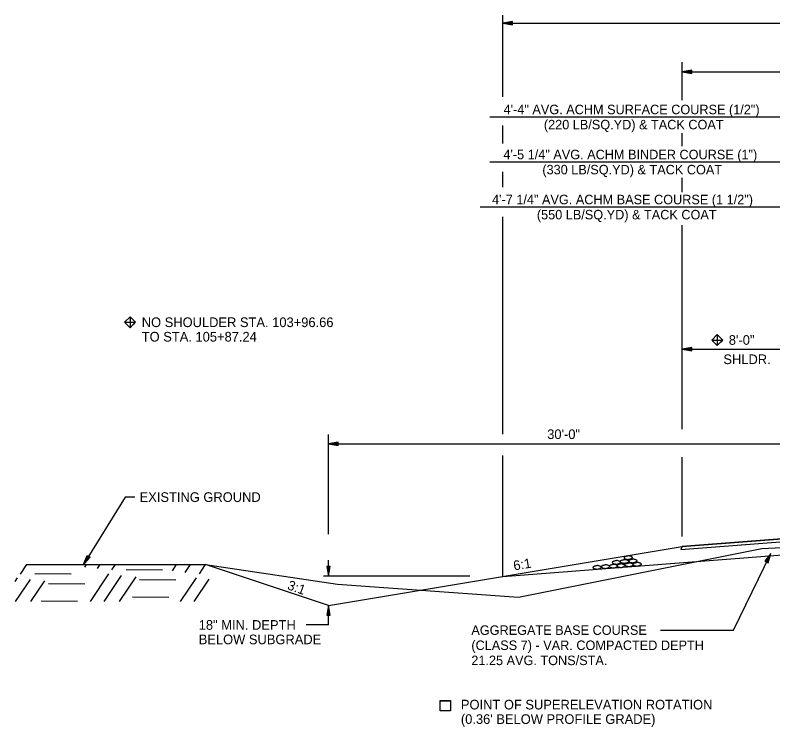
# Model space of a CAD drawing. Extents: x 1001270 to 1003428, y 1840152 to 1842912.
# Drawn here: x 1001282.03 to 1001329.17, y 1842384.9 to 1842429.16 of the extents above; entities that cross this region are included whole.
import ezdxf

# ---------------------------------------------------------------- set-up
doc = ezdxf.new("R2010")
doc.units = 0
for name, color, linetype in [('1', 7, 'Continuous'), ('10', 7, 'Continuous'), ('19', 7, 'Continuous')]:
    doc.layers.add(name, color=color, linetype=linetype)

# ---------------------------------------------------------------- blocks, each defined once
blk = doc.blocks.new('ROCKS')
at = {"layer": '1'}
blk.add_spline([(0.013, 0.06), (0.053, 0.053), (0.107, 0.033), (0.133, 0.013), (0.133, -0.007), (0.12, -0.033), (0.107, -0.04), (0.073, -0.053), (0.033, -0.067), (0.013, -0.067), (-0.02, -0.06), (-0.06, -0.053), (-0.087, -0.047), (-0.113, -0.02), (-0.113, -0.007), (-0.107, 0.02), (-0.087, 0.033), (-0.067, 0.047), (-0.033, 0.053), (-0.02, 0.06), (0.013, 0.06)], degree=3, dxfattribs=at)
blk = doc.blocks.new('4TO1 ABC')
at = {"layer": '1', "xscale": 0.1312491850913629, "yscale": 0.1312491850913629, "rotation": 180}
for p in [(0.00175, -0.00875), (-0.03325, -0.0385), (-0.016625, -0.023625), (0, -0.0385), (0.018375, -0.023625), (0.034125, -0.04025), (0.051625, -0.025375), (0.06475, -0.04025), (0.098, -0.04025), (0.133, -0.041125)]:
    blk.add_blockref('ROCKS', p, dxfattribs=at)

msp = doc.modelspace()

# ---------------------------------------------------------------- linework, layer by layer
at = {"layer": '10'}
for p, q in [((1001289.179, 1842410.399), (1001289.179, 1842409.719)), ((1001288.839, 1842410.059), (1001289.519, 1842410.059)), ((1001289.381, 1842409.921), (1001289.387, 1842409.927)), ((1001325.709, 1842409.294), (1001325.709, 1842408.614)), ((1001325.369, 1842408.954), (1001326.049, 1842408.954)), ((1001325.911, 1842408.816), (1001325.917, 1842408.822))]:
    msp.add_line(p, q, dxfattribs=at)
for points in [[(1001289.387, 1842409.927), (1001289.519, 1842410.059), (1001289.179, 1842410.399), (1001288.839, 1842410.059), (1001289.179, 1842409.719), (1001289.381, 1842409.921)], [(1001325.917, 1842408.822), (1001326.049, 1842408.954), (1001325.709, 1842409.294), (1001325.369, 1842408.954), (1001325.709, 1842408.614), (1001325.911, 1842408.816)]]:
    msp.add_lwpolyline(points, dxfattribs=at)
at = {"layer": '19'}
for p, q in [((1001312.371, 1842424.083), (1001312.371, 1842429.157)), ((1001312.971, 1842428.759), (1001312.371, 1842428.654)), ((1001312.371, 1842428.654), (1001368.525, 1842428.654)), ((1001312.371, 1842428.654), (1001312.971, 1842428.549)), ((1001312.971, 1842428.704), (1001312.531, 1842428.669)), ((1001312.531, 1842428.639), (1001312.971, 1842428.599)), ((1001312.971, 1842428.549), (1001312.971, 1842428.759)), ((1001323.525, 1842423.863), (1001323.525, 1842426.227)), ((1001324.125, 1842425.732), (1001323.525, 1842425.627)), ((1001323.525, 1842425.627), (1001324.125, 1842425.522)), ((1001323.525, 1842425.627), (1001367.525, 1842425.627)), ((1001324.125, 1842425.677), (1001323.685, 1842425.642)), ((1001323.685, 1842425.612), (1001324.125, 1842425.572)), ((1001324.125, 1842425.522), (1001324.125, 1842425.732)), ((1001331.395, 1842422.82), (1001311.553, 1842422.82)), ((1001312.371, 1842421.171), (1001312.371, 1842422.3)), ((1001323.525, 1842421.012), (1001323.525, 1842421.824)), ((1001331.286, 1842420.02), (1001311.553, 1842420.02)), ((1001312.371, 1842418.459), (1001312.371, 1842419.42)), ((1001323.525, 1842418.144), (1001323.525, 1842419.046)), ((1001331.113, 1842417.22), (1001310.964, 1842417.22)), ((1001312.371, 1842403.092), (1001312.371, 1842416.616)), ((1001323.525, 1842403.41), (1001323.525, 1842416.105)), ((1001324.125, 1842408.483), (1001323.525, 1842408.378)), ((1001323.525, 1842408.378), (1001331.525, 1842408.378)), ((1001323.525, 1842408.378), (1001324.125, 1842408.273)), ((1001324.125, 1842408.428), (1001323.685, 1842408.393)), ((1001323.685, 1842408.363), (1001324.125, 1842408.323)), ((1001324.125, 1842408.273), (1001324.125, 1842408.483)), ((1001301.519, 1842396.888), (1001301.519, 1842403.081)), ((1001302.119, 1842402.601), (1001301.519, 1842402.496)), ((1001301.519, 1842402.496), (1001331.519, 1842402.496)), ((1001301.519, 1842402.496), (1001302.119, 1842402.391)), ((1001302.119, 1842402.546), (1001301.679, 1842402.511)), ((1001301.679, 1842402.481), (1001302.119, 1842402.441)), ((1001302.119, 1842402.391), (1001302.119, 1842402.601)), ((1001312.371, 1842394.251), (1001312.371, 1842401.767)), ((1001323.525, 1842396.741), (1001323.525, 1842401.663)), ((1001301.519, 1842392.442), (1001323.525, 1842396.11)), ((1001323.525, 1842396.11), (1001323.438, 1842395.936)), ((1001326.721, 1842390.916), (1001329.041, 1842395.682)), ((1001329.041, 1842395.682), (1001328.677, 1842395.193)), ((1001328.864, 1842395.1), (1001329.041, 1842395.682)), ((1001286.292, 1842394.988), (1001286.516, 1842395.555)), ((1001286.693, 1842395.445), (1001286.292, 1842394.988)), ((1001286.366, 1842395.129), (1001286.559, 1842395.523)), ((1001286.652, 1842395.467), (1001286.389, 1842395.118)), ((1001286.516, 1842395.555), (1001286.693, 1842395.445)), ((1001301.519, 1842394.276), (1001301.519, 1842395.262)), ((1001328.677, 1842395.193), (1001328.864, 1842395.1)), ((1001328.959, 1842395.545), (1001328.726, 1842395.172)), ((1001328.82, 1842395.123), (1001328.984, 1842395.532)), ((1001282.373, 1842394.403), (1001282.764, 1842394.986)), ((1001286.358, 1842394.837), (1001286.464, 1842394.987)), ((1001287.153, 1842394.745), (1001287.319, 1842394.99)), ((1001288.048, 1842394.653), (1001288.274, 1842394.992)), ((1001288.936, 1842394.683), (1001291.196, 1842394.671)), ((1001291.812, 1842394.598), (1001292.074, 1842394.993)), ((1001292.607, 1842394.506), (1001292.939, 1842394.994)), ((1001293.502, 1842394.414), (1001293.883, 1842394.988)), ((1001301.519, 1842392.442), (1001293.883, 1842394.988)), ((1001301.624, 1842394.876), (1001301.414, 1842394.876)), ((1001301.414, 1842394.876), (1001301.519, 1842394.276)), ((1001301.464, 1842394.876), (1001301.504, 1842394.436)), ((1001301.519, 1842394.276), (1001301.624, 1842394.876)), ((1001301.534, 1842394.436), (1001301.569, 1842394.876)), ((1001283.261, 1842394.442), (1001285.521, 1842394.421)), ((1001286.71, 1842392.69), (1001287.862, 1842394.411)), ((1001287.565, 1842392.692), (1001288.657, 1842394.319)), ((1001288.52, 1842392.695), (1001289.552, 1842394.227)), ((1001310.315, 1842394.276), (1001301.204, 1842394.276)), ((1001282.033, 1842393.935), (1001282.187, 1842394.161)), ((1001282.055, 1842392.686), (1001282.982, 1842394.069)), ((1001283.01, 1842392.689), (1001283.877, 1842393.977)), ((1001284.101, 1842393.813), (1001286.361, 1842393.791)), ((1001289.766, 1842394.054), (1001292.036, 1842394.042)), ((1001292.32, 1842392.696), (1001293.316, 1842394.171)), ((1001293.175, 1842392.698), (1001294.111, 1842394.08)), ((1001289.324, 1842392.984), (1001291.584, 1842392.962)), ((1001283.648, 1842392.734), (1001285.919, 1842392.721)), ((1001301.519, 1842392.442), (1001301.414, 1842391.842)), ((1001301.624, 1842391.842), (1001301.519, 1842392.442)), ((1001301.519, 1842391.236), (1001301.519, 1842392.442)), ((1001301.504, 1842392.282), (1001301.469, 1842391.842)), ((1001301.574, 1842391.842), (1001301.534, 1842392.282)), ((1001301.414, 1842391.842), (1001301.624, 1842391.842)), ((1001301.519, 1842391.236), (1001300.136, 1842391.236)), ((1001322.186, 1842390.916), (1001326.721, 1842390.916))]:
    msp.add_line(p, q, dxfattribs=at)
for points in [[(1001282.728, 1842394.989), (1001293.883, 1842394.988), (1001302.082, 1842393.777), (1001313.349, 1842392.957), (1001328.479, 1842395.985), (1001332.634, 1842396.196), (1001337.518, 1842396.687), (1001349.673, 1842397.765), (1001361.518, 1842398.535), (1001365.857, 1842398.933), (1001373.504, 1842399.059), (1001376.059, 1842399.691), (1001380.152, 1842402.606), (1001384.463, 1842404.255), (1001389.111, 1842404.941), (1001392.065, 1842405.156)], [(1001323.525, 1842396.11), (1001349.525, 1842398.112), (1001367.525, 1842399.498)], [(1001289.475, 1842399.187), (1001288.875, 1842399.187), (1001286.292, 1842394.988)], [(1001323.438, 1842395.936), (1001349.525, 1842397.945), (1001367.525, 1842399.331)], [(1001312.371, 1842394.251), (1001337.518, 1842396.187)], [(1001309.108, 1842385.886), (1001308.467, 1842385.886), (1001308.467, 1842386.527), (1001309.108, 1842386.527), (1001309.108, 1842385.886)], [(1001308.471, 1842385.889), (1001308.471, 1842386.53), (1001309.112, 1842386.53), (1001309.112, 1842385.889), (1001308.471, 1842385.889)]]:
    msp.add_lwpolyline(points, dxfattribs=at)
msp.add_lwpolyline([(1001323.525, 1842396.11), (1001323.438, 1842395.936), (1001367.525, 1842399.331), (1001367.525, 1842399.498)], close=True, dxfattribs=at)

# ---------------------------------------------------------------- block references
at = {"layer": '19', "xscale": 14.999970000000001, "yscale": -14.99997, "rotation": -176.47096311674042}
msp.add_blockref('4TO1 ABC', (1001320.172, 1842395.547), dxfattribs=at)

# ---------------------------------------------------------------- texts
at = {"layer": '19'}
for s, height, p in [('4\'-4" AVG. ACHM SURFACE COURSE (1/2")', 0.59001, (1001312.416, 1842422.996)), ('(220 LB/SQ.YD) & TACK COAT', 0.59001, (1001314.922, 1842422.056)), ('4\'-5 1/4" AVG. ACHM BINDER COURSE (1")', 0.59001, (1001312.404, 1842420.196)), ('(330 LB/SQ.YD) & TACK COAT', 0.59001, (1001314.827, 1842419.256)), ('4\'-7 1/4" AVG. ACHM BASE COURSE (1 1/2")', 0.59001, (1001311.698, 1842417.396)), ('(550 LB/SQ.YD) & TACK COAT', 0.59001, (1001314.487, 1842416.456)), ('8\'-0"', 0.6, (1001326.426, 1842408.657)), ('SHLDR.', 0.6, (1001326.089, 1842407.457)), ('30\'-0"', 0.6, (1001315.128, 1842402.796)), ('EXISTING GROUND', 0.6, (1001289.775, 1842398.887)), ('18" MIN. DEPTH', 0.6, (1001293.452, 1842390.936)), ('BELOW SUBGRADE', 0.6, (1001293.452, 1842390.036))]:
    msp.add_text(s, height=height, dxfattribs=at).set_placement(p)
for s, height, rotation, p in [('NO SHOULDER STA. 103+96.66', 0.6, 359.9954, (1001289.908, 1842409.759)), ('TO STA. 105+87.24', 0.6, 359.9954, (1001289.908, 1842408.859)), ('6:1', 0.6, 9.3923, (1001313.073, 1842394.622)), ('3:1', 0.6, 340.4943, (1001298.919, 1842393.468)), ('AGGREGATE BASE COURSE', 0.59001, 360, (1001310.41, 1842390.618)), ('(CLASS 7) - VAR. COMPACTED DEPTH', 0.59001, 360, (1001310.41, 1842389.678)), ('21.25 AVG. TONS/STA.', 0.59001, 360, (1001310.41, 1842388.738)), ('POINT OF SUPERELEVATION ROTATION', 0.6, 359.9954, (1001309.76, 1842385.981)), ("(0.36' BELOW PROFILE GRADE)", 0.6, 359.9954, (1001309.76, 1842385.081))]:
    msp.add_text(s, height=height, rotation=rotation, dxfattribs=at).set_placement(p)

doc.saveas('drawing.dxf')
